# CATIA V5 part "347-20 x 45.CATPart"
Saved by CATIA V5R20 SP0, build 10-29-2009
Part number: 347-20 x 45
Definition: NONE
Nomenclature: 347-20 x 45
Source: Unknown
Description: 347-20 x 45
Bounding box of the stored display mesh (mm): x 0 to 45, y -15 to 15, z -15 to 15
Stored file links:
  C:\Users\Utente\Desktop\IO LAVORO\3D X SITO CF\X SITO\3D files 347\347-20 x 45.CATPart
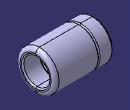
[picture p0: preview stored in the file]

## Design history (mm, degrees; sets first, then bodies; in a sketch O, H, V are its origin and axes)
Body1 "347-20 x 45" (main body)
  Solid1: solid without history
